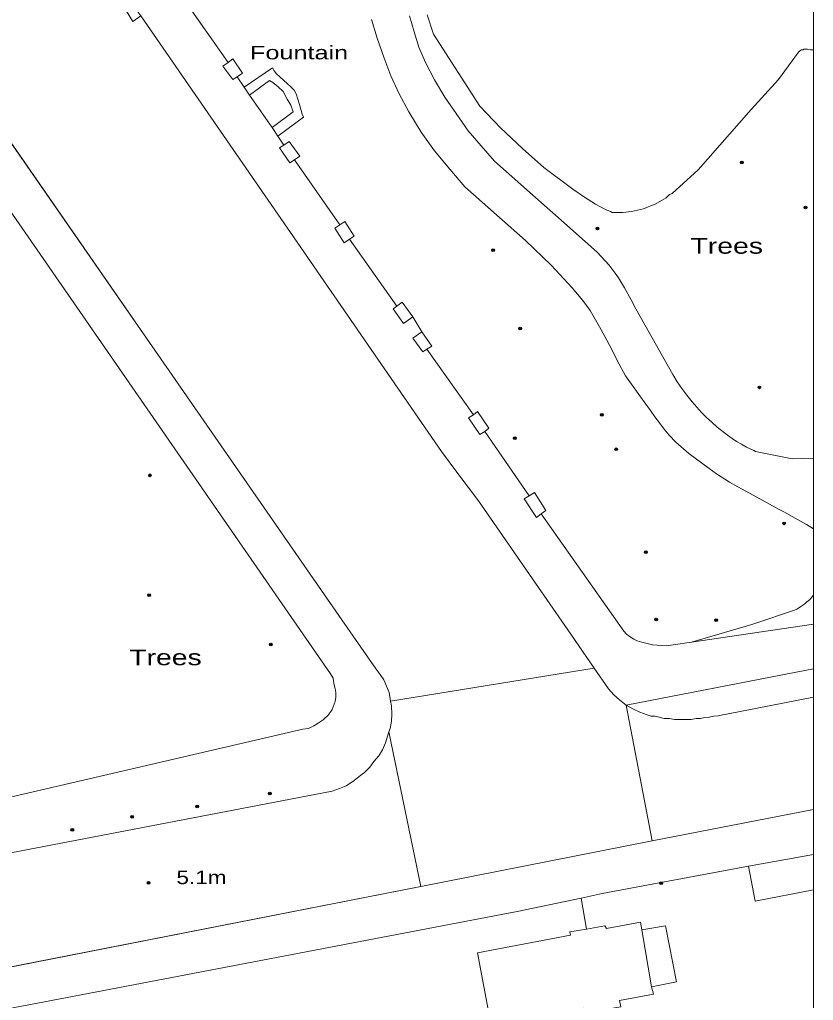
# Model space of a CAD drawing. Extents: x 528790 to 529292, y 179350 to 179856.
# Drawn here: x 529201.8 to 529290.2, y 179559 to 179668.3 of the extents above; entities that cross this region are included whole.
import ezdxf

# ---------------------------------------------------------------- set-up
doc = ezdxf.new("R2010")
doc.units = 0
doc.header["$LTSCALE"] = 0.6
doc.header["$PDMODE"] = 32
doc.header["$PDSIZE"] = 0.3
for name, color, linetype, lineweight in [('1', 7, 'Continuous', 13), ('2', 7, 'Continuous', 13), ('7', 7, 'Continuous', 13)]:
    doc.layers.add(name, color=color, linetype=linetype, lineweight=lineweight)
for name, color, linetype in [('3', 7, 'Continuous'), ('4', 7, 'Continuous'), ('5', 7, 'Continuous')]:
    doc.layers.add(name, color=color, linetype=linetype)

msp = doc.modelspace()

# ---------------------------------------------------------------- linework, layer by layer
at = {"layer": '1'}
for points in [[(529247.2, 179668.8), (529247.9, 179666.65), (529253.05, 179658.65), (529255.35, 179656.2), (529257.8, 179653.9), (529260.2, 179651.8), (529263.4, 179649.4), (529264.7, 179648.5), (529265.95, 179647.7), (529267, 179647.15), (529267.2, 179647.05), (529267.35, 179647), (529267.6, 179646.9), (529267.8, 179646.8), (529269, 179646.8), (529269.95, 179646.9), (529271.3, 179647.2), (529271.8, 179647.4), (529272, 179647.5), (529272.6, 179647.7), (529273.8, 179648.4), (529274.2, 179648.8), (529274.5, 179648.9), (529277.4, 179651.55), (529283.3, 179658.25), (529286.35, 179661.6), (529288.55, 179664.65), (529288.7, 179664.8), (529288.9, 179664.9), (529289.1, 179664.9), (529289.15, 179665), (529289.55, 179665), (529289.9, 179664.9), (529290.22, 179664.9), (529290.22, 179685.931)], [(529215.3, 179668.7), (529231.963, 179644.552), (529248.8, 179620.15), (529250.6, 179617.7), (529252.9, 179614.65), (529256.921, 179608.853), (529263.2, 179599.8), (529265.8, 179596), (529267.4, 179593.7), (529268, 179593.05), (529268.6, 179592.5), (529269.35, 179591.9), (529288.133, 179595.547), (529290.22, 179595.953), (529290.22, 179600.928), (529276.621, 179598.897), (529274.589, 179598.611), (529273.8, 179598.5), (529272.3, 179598.6), (529271.55, 179598.8), (529271.1, 179598.9), (529270.6, 179599.05), (529270.2, 179599.25), (529269.8, 179599.5), (529269.4, 179599.8), (529269.1, 179600.15), (529259.9, 179613.2), (529259.35, 179612.8), (529258, 179614.9), (529258.55, 179615.2), (529253.6, 179622.4), (529253.05, 179622.05), (529251.8, 179623.9), (529252.35, 179624.25), (529247.15, 179631.55), (529246.7, 179631.25), (529245.6, 179632.8), (529246.6, 179633.5), (529245.6, 179635.15), (529244.55, 179634.4), (529243.4, 179636.05), (529243.8, 179636.35), (529238.55, 179643.8), (529237.95, 179643.4), (529236.9, 179645.05), (529237.45, 179645.4), (529232.4, 179652.65), (529231.9, 179652.3), (529230.75, 179654), (529231.2, 179654.3), (529230.55, 179655.3), (529229.9, 179656.25), (529227.4, 179659.85), (529226.8, 179660.75), (529226, 179661.9), (529225.55, 179661.6), (529224.4, 179663.1), (529225, 179663.5), (529220, 179670.65)], [(529220, 179670.65), (529225, 179663.5), (529225.55, 179663.9), (529226.6, 179662.3)], [(529191, 179668.8), (529193.969, 179664.512), (529198.2, 179658.4), (529199.2, 179659.1), (529200, 179658.2), (529198.8, 179657.4), (529215.561, 179633.259), (529238.941, 179599.585), (529241.5, 179595.9), (529241.95, 179595.3), (529242.35, 179594.7), (529242.95, 179593.3), (529243.05, 179592.6), (529243.1, 179592.32), (529265.8, 179596), (529263.2, 179599.8), (529256.921, 179608.853), (529252.9, 179614.65), (529250.6, 179617.7), (529248.8, 179620.15), (529231.963, 179644.552), (529215.3, 179668.7), (529214.4, 179668.05), (529213.7, 179669.2)], [(529241, 179668.3), (529241.6, 179666.2), (529242.35, 179664.1), (529243.15, 179662), (529244.05, 179660), (529245.15, 179658), (529246.5, 179655.75), (529248, 179653.65), (529249.7, 179651.6), (529251.4, 179649.65), (529258.15, 179643.65), (529261, 179640.9), (529261.974, 179639.872), (529263.349, 179638.384), (529263.955, 179637.695), (529264.531, 179636.981), (529265.344, 179635.865), (529266.524, 179633.776), (529267.207, 179632.567), (529267.797, 179631.431), (529268.369, 179630.285), (529269.3, 179628.6), (529271.545, 179625.442), (529272.055, 179624.741), (529272.561, 179624.035), (529273.071, 179623.334), (529273.597, 179622.646), (529274.148, 179621.98), (529274.886, 179621.191), (529276.344, 179619.92), (529278.594, 179618.274), (529279.439, 179617.681), (529280.89, 179616.742), (529281.788, 179616.235), (529283.905, 179615.051), (529286.406, 179613.694), (529286.909, 179613.418), (529289.463, 179612.014), (529290.22, 179611.524), (529290.22, 179619.427), (529287.842, 179619.351), (529283.775, 179620.174), (529283.589, 179620.261), (529282.768, 179620.647), (529282.198, 179620.96), (529281.67, 179621.28), (529281.154, 179621.619), (529280.648, 179621.974), (529279.489, 179622.88), (529278.892, 179623.406), (529278.315, 179623.953), (529277.755, 179624.519), (529276.703, 179625.694), (529276.124, 179626.417), (529275.575, 179627.163), (529275.056, 179627.931), (529274.569, 179628.719), (529274.085, 179629.574), (529270.42, 179636.054), (529269.93, 179637.04), (529269.181, 179638.379), (529268.841, 179638.941), (529268.491, 179639.497), (529268.125, 179640.042), (529267.463, 179640.918), (529267.035, 179641.416), (529266.586, 179641.896), (529266.119, 179642.357), (529261.475, 179646.486), (529260.55, 179647.3), (529254.7, 179652.5), (529253.2, 179654.2), (529251.75, 179655.9), (529250.4, 179657.8), (529249.15, 179659.65), (529248, 179661.55), (529247, 179663.5), (529246.25, 179665.2), (529245.75, 179666.9), (529245.2, 179668.7)], [(529290.22, 179604.13), (529290.22, 179611.524), (529289.463, 179612.014), (529286.909, 179613.418), (529286.406, 179613.694), (529283.905, 179615.051), (529281.788, 179616.235), (529280.89, 179616.742), (529279.439, 179617.681), (529278.594, 179618.274), (529276.344, 179619.92), (529274.886, 179621.191), (529274.148, 179621.98), (529273.597, 179622.646), (529273.071, 179623.334), (529272.561, 179624.035), (529272.055, 179624.741), (529271.545, 179625.442), (529269.3, 179628.6), (529268.369, 179630.285), (529267.797, 179631.431), (529267.207, 179632.567), (529266.524, 179633.776), (529265.344, 179635.865), (529264.531, 179636.981), (529263.955, 179637.695), (529263.349, 179638.384), (529261.974, 179639.872), (529261, 179640.9), (529258.15, 179643.65), (529251.4, 179649.65), (529249.7, 179651.6), (529248, 179653.65), (529246.5, 179655.75), (529245.15, 179658), (529244.05, 179660), (529243.15, 179662), (529242.35, 179664.1), (529241.6, 179666.2), (529241, 179668.3)], [(529245.2, 179668.7), (529245.75, 179666.9), (529246.25, 179665.2), (529247, 179663.5), (529248, 179661.55), (529249.15, 179659.65), (529250.4, 179657.8), (529251.75, 179655.9), (529253.2, 179654.2), (529254.7, 179652.5), (529260.55, 179647.3), (529261.475, 179646.486), (529266.119, 179642.357), (529266.586, 179641.896), (529267.035, 179641.416), (529267.463, 179640.918), (529268.125, 179640.042), (529268.491, 179639.497), (529268.841, 179638.941), (529269.181, 179638.379), (529269.93, 179637.04), (529270.42, 179636.054), (529274.085, 179629.574), (529274.569, 179628.719), (529275.056, 179627.931), (529275.575, 179627.163), (529276.124, 179626.417), (529276.703, 179625.694), (529277.755, 179624.519)], [(529290.22, 179619.427), (529290.22, 179664.9), (529289.9, 179664.9), (529289.55, 179665), (529289.15, 179665), (529289.1, 179664.9), (529288.9, 179664.9), (529288.7, 179664.8), (529288.55, 179664.65), (529286.35, 179661.6), (529283.3, 179658.25), (529277.4, 179651.55), (529274.5, 179648.9), (529274.2, 179648.8), (529273.8, 179648.4), (529272.6, 179647.7), (529272, 179647.5), (529271.8, 179647.4), (529271.3, 179647.2), (529269.95, 179646.9), (529269, 179646.8), (529267.8, 179646.8), (529267.6, 179646.9), (529267.35, 179647), (529267.2, 179647.05), (529267, 179647.15), (529265.95, 179647.7), (529264.7, 179648.5), (529263.4, 179649.4), (529260.2, 179651.8), (529257.8, 179653.9), (529255.35, 179656.2), (529253.05, 179658.65), (529247.9, 179666.65), (529247.2, 179668.8)], [(529226.6, 179662.3), (529226, 179661.9), (529226.8, 179660.75), (529229.95, 179662.9), (529230.15, 179662.55), (529230.4, 179662.25), (529231.6, 179661.15), (529232, 179660.8), (529232.35, 179660.4), (529232.6, 179660), (529232.95, 179658.8), (529233.25, 179657.75), (529233.4, 179657.4), (529230.55, 179655.3), (529231.2, 179654.3), (529231.8, 179654.7), (529233, 179653.05), (529232.4, 179652.65), (529237.45, 179645.4), (529238, 179645.8), (529239.05, 179644.15), (529238.55, 179643.8), (529243.8, 179636.35), (529244.4, 179636.8), (529245.6, 179635.15), (529246.6, 179633.5), (529247.7, 179631.9), (529247.15, 179631.55), (529252.35, 179624.25), (529252.8, 179624.6), (529254.05, 179622.75), (529253.6, 179622.4), (529258.55, 179615.2), (529259.15, 179615.6), (529260.4, 179613.6), (529259.9, 179613.2), (529269.1, 179600.15), (529269.4, 179599.8), (529269.8, 179599.5), (529270.2, 179599.25), (529270.6, 179599.05), (529271.1, 179598.9), (529271.55, 179598.8), (529272.3, 179598.6), (529273.8, 179598.5), (529274.589, 179598.611), (529276.621, 179598.897), (529283.355, 179600.864), (529283.689, 179600.976), (529288.124, 179602.466), (529288.362, 179602.591), (529288.595, 179602.726), (529288.667, 179602.771), (529288.823, 179602.87), (529289.044, 179603.024), (529289.259, 179603.187), (529289.467, 179603.358), (529289.702, 179603.57), (529289.924, 179603.791), (529290.134, 179604.024), (529290.22, 179604.13)], [(529163.2, 179568.25), (529236.6, 179582.3), (529237.4, 179582.6), (529238.15, 179582.9), (529238.9, 179583.4), (529239.929, 179584.192), (529240.2, 179584.4), (529240.8, 179585), (529241.25, 179585.6), (529241.8, 179586.25), (529242.2, 179586.9), (529242.55, 179587.7), (529242.93, 179588.92), (529243.05, 179589.3), (529243.2, 179590.1), (529243.25, 179590.9), (529243.2, 179591.8), (529243.1, 179592.32), (529243.05, 179592.6), (529242.95, 179593.3), (529242.35, 179594.7), (529241.95, 179595.3), (529241.5, 179595.9), (529238.941, 179599.585), (529215.561, 179633.259), (529198.8, 179657.4)], [(529195.2, 179654.9), (529236.4, 179595.4), (529236.7, 179594.9), (529236.8, 179594.3), (529236.95, 179593.75), (529237, 179593.3), (529237, 179592.8), (529236.95, 179592.3), (529236.6, 179591.4), (529236.2, 179590.8), (529235.6, 179590.25), (529235.05, 179589.9), (529234.55, 179589.6), (529233.95, 179589.3), (529233.35, 179589.2), (529161.4, 179572.5)], [(529161.4, 179572.5), (529233.35, 179589.2), (529233.95, 179589.3), (529234.55, 179589.6), (529235.05, 179589.9), (529235.6, 179590.25), (529236.2, 179590.8), (529236.6, 179591.4), (529236.95, 179592.3), (529237, 179592.8), (529237, 179593.3), (529236.95, 179593.75), (529236.8, 179594.3), (529236.7, 179594.9), (529236.4, 179595.4), (529195.2, 179654.9)], [(529277.755, 179624.519), (529278.315, 179623.953), (529278.892, 179623.406), (529279.489, 179622.88), (529280.648, 179621.974), (529281.154, 179621.619), (529281.67, 179621.28), (529282.198, 179620.96), (529282.768, 179620.647), (529283.589, 179620.261), (529283.775, 179620.174), (529287.842, 179619.351), (529290.22, 179619.427)], [(529290.22, 179534.231), (529290.22, 179571.313), (529283.75, 179570.05), (529283, 179573.95), (529266.7, 179570.9), (529264.35, 179570.4), (529264.95, 179566.95), (529267, 179567.3), (529267.15, 179567), (529270.95, 179567.7), (529271.1, 179566.85), (529273.75, 179567.3), (529274.95, 179561.05), (529272.2, 179560.5), (529272.4, 179559.7), (529268.6, 179559), (529268.75, 179558.3)], [(529254.2, 179556.8), (529252.8, 179564.3), (529263.15, 179566.25), (529263.1, 179566.65), (529264.95, 179566.95), (529264.35, 179570.4), (529257.2, 179568.9), (529202.8, 179558.5)]]:
    msp.add_lwpolyline(points, dxfattribs=at)
for points in [[(529214.4, 179669.7), (529213.7, 179669.2), (529214.4, 179668.05), (529215.3, 179668.7), (529214.85, 179669.3), (529214.55, 179669.8)], [(529226, 179661.9), (529226.6, 179662.3), (529225.55, 179663.9), (529225, 179663.5), (529224.4, 179663.1), (529225.55, 179661.6)], [(529227.4, 179659.85), (529229.6, 179661.5), (529230, 179661.25), (529230.6, 179660.8), (529231.15, 179660.25), (529231.6, 179659.4), (529232, 179658.75), (529232.25, 179658), (529229.9, 179656.25), (529230.55, 179655.3), (529233.4, 179657.4), (529233.25, 179657.75), (529232.95, 179658.8), (529232.6, 179660), (529232.35, 179660.4), (529232, 179660.8), (529231.6, 179661.15), (529230.4, 179662.25), (529230.15, 179662.55), (529229.95, 179662.9), (529226.8, 179660.75)], [(529229.9, 179656.25), (529232.25, 179658), (529232, 179658.75), (529231.6, 179659.4), (529231.15, 179660.25), (529230.6, 179660.8), (529230, 179661.25), (529229.6, 179661.5), (529227.4, 179659.85)], [(529229.9, 179656.25), (529232.25, 179658), (529232, 179658.75), (529231.6, 179659.4), (529231.15, 179660.25), (529230.6, 179660.8), (529230, 179661.25), (529229.6, 179661.5), (529227.4, 179659.85)], [(529232.4, 179652.65), (529233, 179653.05), (529231.8, 179654.7), (529231.2, 179654.3), (529230.75, 179654), (529231.9, 179652.3)], [(529238.55, 179643.8), (529239.05, 179644.15), (529238, 179645.8), (529237.45, 179645.4), (529236.9, 179645.05), (529237.95, 179643.4)], [(529245.6, 179635.15), (529244.4, 179636.8), (529243.8, 179636.35), (529243.4, 179636.05), (529244.55, 179634.4)], [(529247.15, 179631.55), (529247.7, 179631.9), (529246.6, 179633.5), (529245.6, 179632.8), (529246.7, 179631.25)], [(529252.35, 179624.25), (529251.8, 179623.9), (529253.05, 179622.05), (529253.6, 179622.4), (529254.05, 179622.75), (529252.8, 179624.6)], [(529259.9, 179613.2), (529260.4, 179613.6), (529259.15, 179615.6), (529258.55, 179615.2), (529258, 179614.9), (529259.35, 179612.8)], [(529290.22, 179600.928), (529290.22, 179604.13), (529290.134, 179604.024), (529289.924, 179603.791), (529289.702, 179603.57), (529289.467, 179603.358), (529289.259, 179603.187), (529289.044, 179603.024), (529288.823, 179602.87), (529288.667, 179602.771), (529288.595, 179602.726), (529288.362, 179602.591), (529288.124, 179602.466), (529283.689, 179600.976), (529283.355, 179600.864), (529276.621, 179598.897)], [(529272.27, 179576.76), (529269.35, 179591.9), (529268.6, 179592.5), (529268, 179593.05), (529267.4, 179593.7), (529265.8, 179596), (529243.1, 179592.32), (529243.2, 179591.8), (529243.25, 179590.9), (529243.2, 179590.1), (529243.05, 179589.3), (529242.93, 179588.92), (529246.48, 179571.7)], [(529290.22, 179595.953), (529288.133, 179595.547), (529269.35, 179591.9), (529270.1, 179591.5), (529270.9, 179591.1), (529271.7, 179590.8), (529272.15, 179590.65), (529272.6, 179590.65), (529273.6, 179590.4), (529274.2, 179590.4), (529274.75, 179590.3), (529276.6, 179590.3), (529277.15, 179590.4), (529277.6, 179590.4), (529278.15, 179590.5), (529278.6, 179590.55), (529279.1, 179590.65), (529279.6, 179590.7), (529280.1, 179590.8), (529280.55, 179590.9), (529290.22, 179592.78)], [(529290.22, 179592.78), (529280.55, 179590.9), (529280.1, 179590.8), (529279.6, 179590.7), (529279.1, 179590.65), (529278.6, 179590.55), (529278.15, 179590.5), (529277.6, 179590.4), (529277.15, 179590.4), (529276.6, 179590.3), (529274.75, 179590.3), (529274.2, 179590.4), (529273.6, 179590.4), (529272.6, 179590.65), (529272.15, 179590.65), (529271.7, 179590.8), (529270.9, 179591.1), (529270.1, 179591.5), (529269.35, 179591.9), (529272.27, 179576.76), (529290.22, 179580.282)], [(529246.48, 179571.7), (529242.93, 179588.92), (529242.55, 179587.7), (529242.2, 179586.9), (529241.8, 179586.25), (529241.25, 179585.6), (529240.8, 179585), (529240.2, 179584.4), (529239.929, 179584.192), (529238.9, 179583.4), (529238.15, 179582.9), (529237.4, 179582.6), (529236.6, 179582.3), (529163.2, 179568.25), (529162.75, 179568.05), (529163.652, 179562), (529164.6, 179555.64)], [(529290.22, 179575.267), (529290.22, 179580.282), (529272.27, 179576.76), (529246.48, 179571.7), (529164.6, 179555.64), (529165.2, 179555.55), (529165, 179554.6), (529164.6, 179554.65), (529164.1, 179551.9), (529164.6, 179551.8), (529164.5, 179551.5), (529182.8, 179554.8), (529202.8, 179558.5), (529257.2, 179568.9), (529264.35, 179570.4), (529266.7, 179570.9), (529283, 179573.95)], [(529290.22, 179575.267), (529283, 179573.95), (529283.75, 179570.05), (529290.22, 179571.313)], [(529272.2, 179560.5), (529271.1, 179566.85), (529270.95, 179567.7), (529267.15, 179567), (529267, 179567.3), (529264.95, 179566.95), (529263.1, 179566.65), (529263.15, 179566.25), (529252.8, 179564.3), (529254.2, 179556.8), (529254.25, 179556.25), (529264.6, 179558.15), (529264.7, 179557.6), (529268.75, 179558.3), (529268.6, 179559), (529272.4, 179559.7)], [(529272.2, 179560.5), (529274.95, 179561.05), (529273.75, 179567.3), (529271.1, 179566.85)]]:
    msp.add_lwpolyline(points, close=True, dxfattribs=at)
at = {"layer": '2'}
for p, q in [((529225, 179663.5), (529220, 179670.65)), ((529231.963, 179644.552), (529215.3, 179668.7)), ((529226.8, 179660.75), (529226, 179661.9)), ((529227.4, 179659.85), (529226.8, 179660.75)), ((529229.9, 179656.25), (529227.4, 179659.85)), ((529198.8, 179657.4), (529215.561, 179633.259)), ((529230.55, 179655.3), (529229.9, 179656.25)), ((529231.2, 179654.3), (529230.55, 179655.3)), ((529237.45, 179645.4), (529232.4, 179652.65)), ((529243.8, 179636.35), (529238.55, 179643.8)), ((529246.6, 179633.5), (529245.6, 179635.15)), ((529215.561, 179633.259), (529238.941, 179599.585)), ((529252.35, 179624.25), (529247.15, 179631.55)), ((529258.55, 179615.2), (529253.6, 179622.4)), ((529290.22, 179600.928), (529276.621, 179598.897)), ((529243.1, 179592.32), (529265.8, 179596)), ((529269.35, 179591.9), (529272.27, 179576.76)), ((529242.93, 179588.92), (529246.48, 179571.7)), ((529272.27, 179576.76), (529290.22, 179580.282)), ((529246.48, 179571.7), (529272.27, 179576.76)), ((529283, 179573.95), (529290.22, 179575.267)), ((529164.6, 179555.64), (529246.48, 179571.7)), ((529264.95, 179566.95), (529264.35, 179570.4)), ((529271.1, 179566.85), (529272.2, 179560.5))]:
    msp.add_line(p, q, dxfattribs=at)
for points in [[(529215.3, 179668.7), (529214.4, 179668.05), (529213.7, 179669.2), (529214.4, 179669.7)], [(529266.524, 179633.776), (529265.344, 179635.865), (529264.531, 179636.981), (529263.955, 179637.695), (529263.349, 179638.384), (529261.974, 179639.872), (529261, 179640.9), (529258.15, 179643.65), (529251.4, 179649.65), (529249.7, 179651.6), (529248, 179653.65), (529246.5, 179655.75), (529245.15, 179658), (529244.05, 179660), (529243.15, 179662), (529242.35, 179664.1), (529241.6, 179666.2), (529241, 179668.3)], [(529245.2, 179668.7), (529245.75, 179666.9), (529246.25, 179665.2), (529247, 179663.5), (529248, 179661.55), (529249.15, 179659.65), (529250.4, 179657.8), (529251.75, 179655.9), (529253.2, 179654.2), (529254.7, 179652.5), (529260.55, 179647.3), (529261.475, 179646.486)], [(529247.2, 179668.8), (529247.9, 179666.65), (529253.05, 179658.65), (529255.35, 179656.2), (529257.8, 179653.9), (529260.2, 179651.8), (529263.4, 179649.4), (529264.7, 179648.5), (529265.95, 179647.7), (529267, 179647.15), (529267.2, 179647.05), (529267.35, 179647), (529267.6, 179646.9), (529267.8, 179646.8), (529269, 179646.8), (529269.95, 179646.9), (529271.3, 179647.2), (529271.8, 179647.4), (529272, 179647.5), (529272.6, 179647.7), (529273.8, 179648.4), (529274.2, 179648.8), (529274.5, 179648.9), (529277.4, 179651.55), (529283.3, 179658.25), (529286.35, 179661.6), (529288.55, 179664.65), (529288.7, 179664.8), (529288.9, 179664.9), (529289.1, 179664.9), (529289.15, 179665), (529289.55, 179665), (529289.9, 179664.9), (529290.22, 179664.9)], [(529226, 179661.9), (529225.55, 179661.6), (529224.4, 179663.1), (529225, 179663.5)], [(529225, 179663.5), (529225.55, 179663.9), (529226.6, 179662.3), (529226, 179661.9)], [(529226.8, 179660.75), (529229.95, 179662.9), (529230.15, 179662.55), (529230.4, 179662.25), (529231.6, 179661.15), (529232, 179660.8), (529232.35, 179660.4), (529232.6, 179660), (529232.95, 179658.8), (529233.25, 179657.75), (529233.4, 179657.4), (529230.55, 179655.3)], [(529227.4, 179659.85), (529229.6, 179661.5), (529230, 179661.25), (529230.6, 179660.8), (529231.15, 179660.25), (529231.6, 179659.4), (529232, 179658.75), (529232.25, 179658), (529229.9, 179656.25)], [(529195.2, 179654.9), (529236.4, 179595.4), (529236.7, 179594.9), (529236.8, 179594.3), (529236.95, 179593.75), (529237, 179593.3), (529237, 179592.8), (529236.95, 179592.3), (529236.6, 179591.4), (529236.2, 179590.8), (529235.6, 179590.25), (529235.05, 179589.9), (529234.55, 179589.6), (529233.95, 179589.3), (529233.35, 179589.2), (529161.4, 179572.5)], [(529231.2, 179654.3), (529231.8, 179654.7), (529233, 179653.05), (529232.4, 179652.65)], [(529232.4, 179652.65), (529231.9, 179652.3), (529230.75, 179654), (529231.2, 179654.3)], [(529290.22, 179619.427), (529287.842, 179619.351), (529283.775, 179620.174), (529283.589, 179620.261), (529282.768, 179620.647), (529282.198, 179620.96), (529281.67, 179621.28), (529281.154, 179621.619), (529280.648, 179621.974), (529279.489, 179622.88), (529278.892, 179623.406), (529278.315, 179623.953), (529277.755, 179624.519), (529276.703, 179625.694), (529276.124, 179626.417), (529275.575, 179627.163), (529275.056, 179627.931), (529274.569, 179628.719), (529274.085, 179629.574), (529270.42, 179636.054), (529269.93, 179637.04), (529269.181, 179638.379), (529268.841, 179638.941), (529268.491, 179639.497), (529268.125, 179640.042), (529267.463, 179640.918), (529267.035, 179641.416), (529266.586, 179641.896), (529266.119, 179642.357), (529261.475, 179646.486)], [(529238.55, 179643.8), (529237.95, 179643.4), (529236.9, 179645.05), (529237.45, 179645.4)], [(529237.45, 179645.4), (529238, 179645.8), (529239.05, 179644.15), (529238.55, 179643.8)], [(529256.921, 179608.853), (529252.9, 179614.65), (529250.6, 179617.7), (529248.8, 179620.15), (529231.963, 179644.552)], [(529245.6, 179635.15), (529244.55, 179634.4), (529243.4, 179636.05), (529243.8, 179636.35)], [(529243.8, 179636.35), (529244.4, 179636.8), (529245.6, 179635.15)], [(529247.15, 179631.55), (529246.7, 179631.25), (529245.6, 179632.8), (529246.6, 179633.5)], [(529246.6, 179633.5), (529247.7, 179631.9), (529247.15, 179631.55)], [(529290.22, 179611.524), (529289.463, 179612.014), (529286.909, 179613.418), (529286.406, 179613.694), (529283.905, 179615.051), (529281.788, 179616.235), (529280.89, 179616.742), (529279.439, 179617.681), (529278.594, 179618.274), (529276.344, 179619.92), (529274.886, 179621.191), (529274.148, 179621.98), (529273.597, 179622.646), (529273.071, 179623.334), (529272.561, 179624.035), (529272.055, 179624.741), (529271.545, 179625.442), (529269.3, 179628.6), (529268.369, 179630.285), (529267.797, 179631.431), (529267.207, 179632.567), (529266.524, 179633.776)], [(529253.6, 179622.4), (529253.05, 179622.05), (529251.8, 179623.9), (529252.35, 179624.25)], [(529252.35, 179624.25), (529252.8, 179624.6), (529254.05, 179622.75), (529253.6, 179622.4)], [(529258.55, 179615.2), (529259.15, 179615.6), (529260.4, 179613.6), (529259.9, 179613.2)], [(529259.9, 179613.2), (529259.35, 179612.8), (529258, 179614.9), (529258.55, 179615.2)], [(529259.9, 179613.2), (529269.1, 179600.15), (529269.4, 179599.8), (529269.8, 179599.5), (529270.2, 179599.25), (529270.6, 179599.05), (529271.1, 179598.9), (529271.55, 179598.8), (529272.3, 179598.6), (529273.8, 179598.5), (529274.589, 179598.611), (529276.621, 179598.897)], [(529265.8, 179596), (529263.2, 179599.8), (529256.921, 179608.853)], [(529276.621, 179598.897), (529283.355, 179600.864), (529283.689, 179600.976), (529288.124, 179602.466), (529288.362, 179602.591), (529288.595, 179602.726), (529288.667, 179602.771), (529288.823, 179602.87), (529289.044, 179603.024), (529289.259, 179603.187), (529289.467, 179603.358), (529289.702, 179603.57), (529289.924, 179603.791), (529290.134, 179604.024), (529290.22, 179604.13)], [(529238.941, 179599.585), (529241.5, 179595.9), (529241.95, 179595.3), (529242.35, 179594.7), (529242.95, 179593.3), (529243.05, 179592.6), (529243.1, 179592.32)], [(529269.35, 179591.9), (529268.6, 179592.5), (529268, 179593.05), (529267.4, 179593.7), (529265.8, 179596)], [(529269.35, 179591.9), (529288.133, 179595.547), (529290.22, 179595.953)], [(529290.22, 179592.78), (529280.55, 179590.9), (529280.1, 179590.8), (529279.6, 179590.7), (529279.1, 179590.65), (529278.6, 179590.55), (529278.15, 179590.5), (529277.6, 179590.4), (529277.15, 179590.4), (529276.6, 179590.3), (529274.75, 179590.3), (529274.2, 179590.4), (529273.6, 179590.4), (529272.6, 179590.65), (529272.15, 179590.65), (529271.7, 179590.8), (529270.9, 179591.1), (529270.1, 179591.5), (529269.35, 179591.9)], [(529243.1, 179592.32), (529243.2, 179591.8), (529243.25, 179590.9), (529243.2, 179590.1), (529243.05, 179589.3), (529242.93, 179588.92)], [(529242.93, 179588.92), (529242.55, 179587.7), (529242.2, 179586.9), (529241.8, 179586.25), (529241.25, 179585.6), (529240.8, 179585), (529240.2, 179584.4), (529239.929, 179584.192)], [(529239.929, 179584.192), (529238.9, 179583.4), (529238.15, 179582.9), (529237.4, 179582.6), (529236.6, 179582.3), (529163.2, 179568.25)], [(529264.35, 179570.4), (529266.7, 179570.9), (529283, 179573.95)], [(529283, 179573.95), (529283.75, 179570.05), (529290.22, 179571.313)], [(529164.5, 179551.5), (529182.8, 179554.8), (529202.8, 179558.5), (529257.2, 179568.9), (529264.35, 179570.4)], [(529264.95, 179566.95), (529267, 179567.3), (529267.15, 179567), (529270.95, 179567.7), (529271.1, 179566.85)], [(529271.1, 179566.85), (529273.75, 179567.3), (529274.95, 179561.05), (529272.2, 179560.5)], [(529254.2, 179556.8), (529252.8, 179564.3), (529263.15, 179566.25), (529263.1, 179566.65), (529264.95, 179566.95)], [(529272.2, 179560.5), (529272.4, 179559.7), (529268.6, 179559), (529268.75, 179558.3), (529264.7, 179557.6), (529264.6, 179558.15), (529254.25, 179556.25), (529254.2, 179556.8)]]:
    msp.add_lwpolyline(points, dxfattribs=at)
at = {"layer": '3'}
for p in [(529282.25, 179652.35), (529289.35, 179647.35), (529266.15, 179645), (529254.55, 179642.6), (529257.55, 179633.85), (529284.2, 179627.3), (529266.65, 179624.25), (529256.95, 179621.65), (529268.25, 179620.4), (529216.3, 179617.5), (529286.95, 179612.15), (529271.55, 179608.95), (529216.2, 179604.15), (529272.7, 179601.45), (529279.4, 179601.35), (529229.75, 179598.65), (529229.65, 179582.05), (529221.55, 179580.6), (529214.3, 179579.45), (529207.65, 179578), (529216.15, 179572.1)]:
    msp.add_point(p, dxfattribs=at)
at = {"layer": '4'}
msp.add_point((529273.25, 179572.05), dxfattribs=at)
at = {"layer": '7'}
msp.add_lwpolyline([(528790.22, 179356.024), (529290.22, 179356.024), (529290.22, 179856.024), (528790.22, 179856.024)], close=True, dxfattribs=at)

# ---------------------------------------------------------------- texts
at = {"layer": '5'}
for s, height, width, p in [('Fountain', 1.5, 1.4, (529227.45, 179663.85)), ('Trees', 1.75, 1.35, (529276.53, 179642.19)), ('Trees', 1.75, 1.35, (529213.99, 179596.34)), ('5.1m', 1.5, 1.25, (529219.25, 179571.95))]:
    msp.add_text(s, height=height, dxfattribs=dict(at, width=width)).set_placement(p)

doc.saveas('drawing.dxf')
